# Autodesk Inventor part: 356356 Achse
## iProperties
Created: 2006-10
Part Number: 356356 Achse
Material: 1.0718.07
Description: Bolzen
Document SubType Name: Modeling
Designer: OSchmidt
Density: 7.84 g/cm^3
Abmessung: Rd. 12
HalbzeugNorm: DIN 671
Zweck: 266450
Author: OSchmidt
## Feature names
1. Extrusion2
2. Extrusion5
3. Bohrung1 [Hole]
